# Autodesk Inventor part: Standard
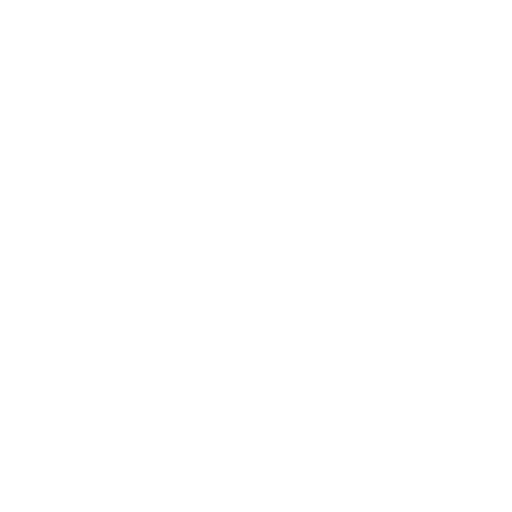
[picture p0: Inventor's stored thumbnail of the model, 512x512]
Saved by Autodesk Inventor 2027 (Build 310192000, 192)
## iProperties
Created: 2005-05
Part Number: Standard
Document SubType Name: Modeling
Designer: JWe
Density: 1 g/cm^3
Material: Generic
Appearance: Default
Author: JWe
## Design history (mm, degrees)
